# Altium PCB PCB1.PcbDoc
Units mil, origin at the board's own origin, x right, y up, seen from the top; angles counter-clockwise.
Board outline 3959.97 x 4064.97 mil, 2 copper layers (Top Layer, Bottom Layer); 11 components, 12 nets, 153 pads, 2 vias.
Unrouted connection lines stored in the file: 4.
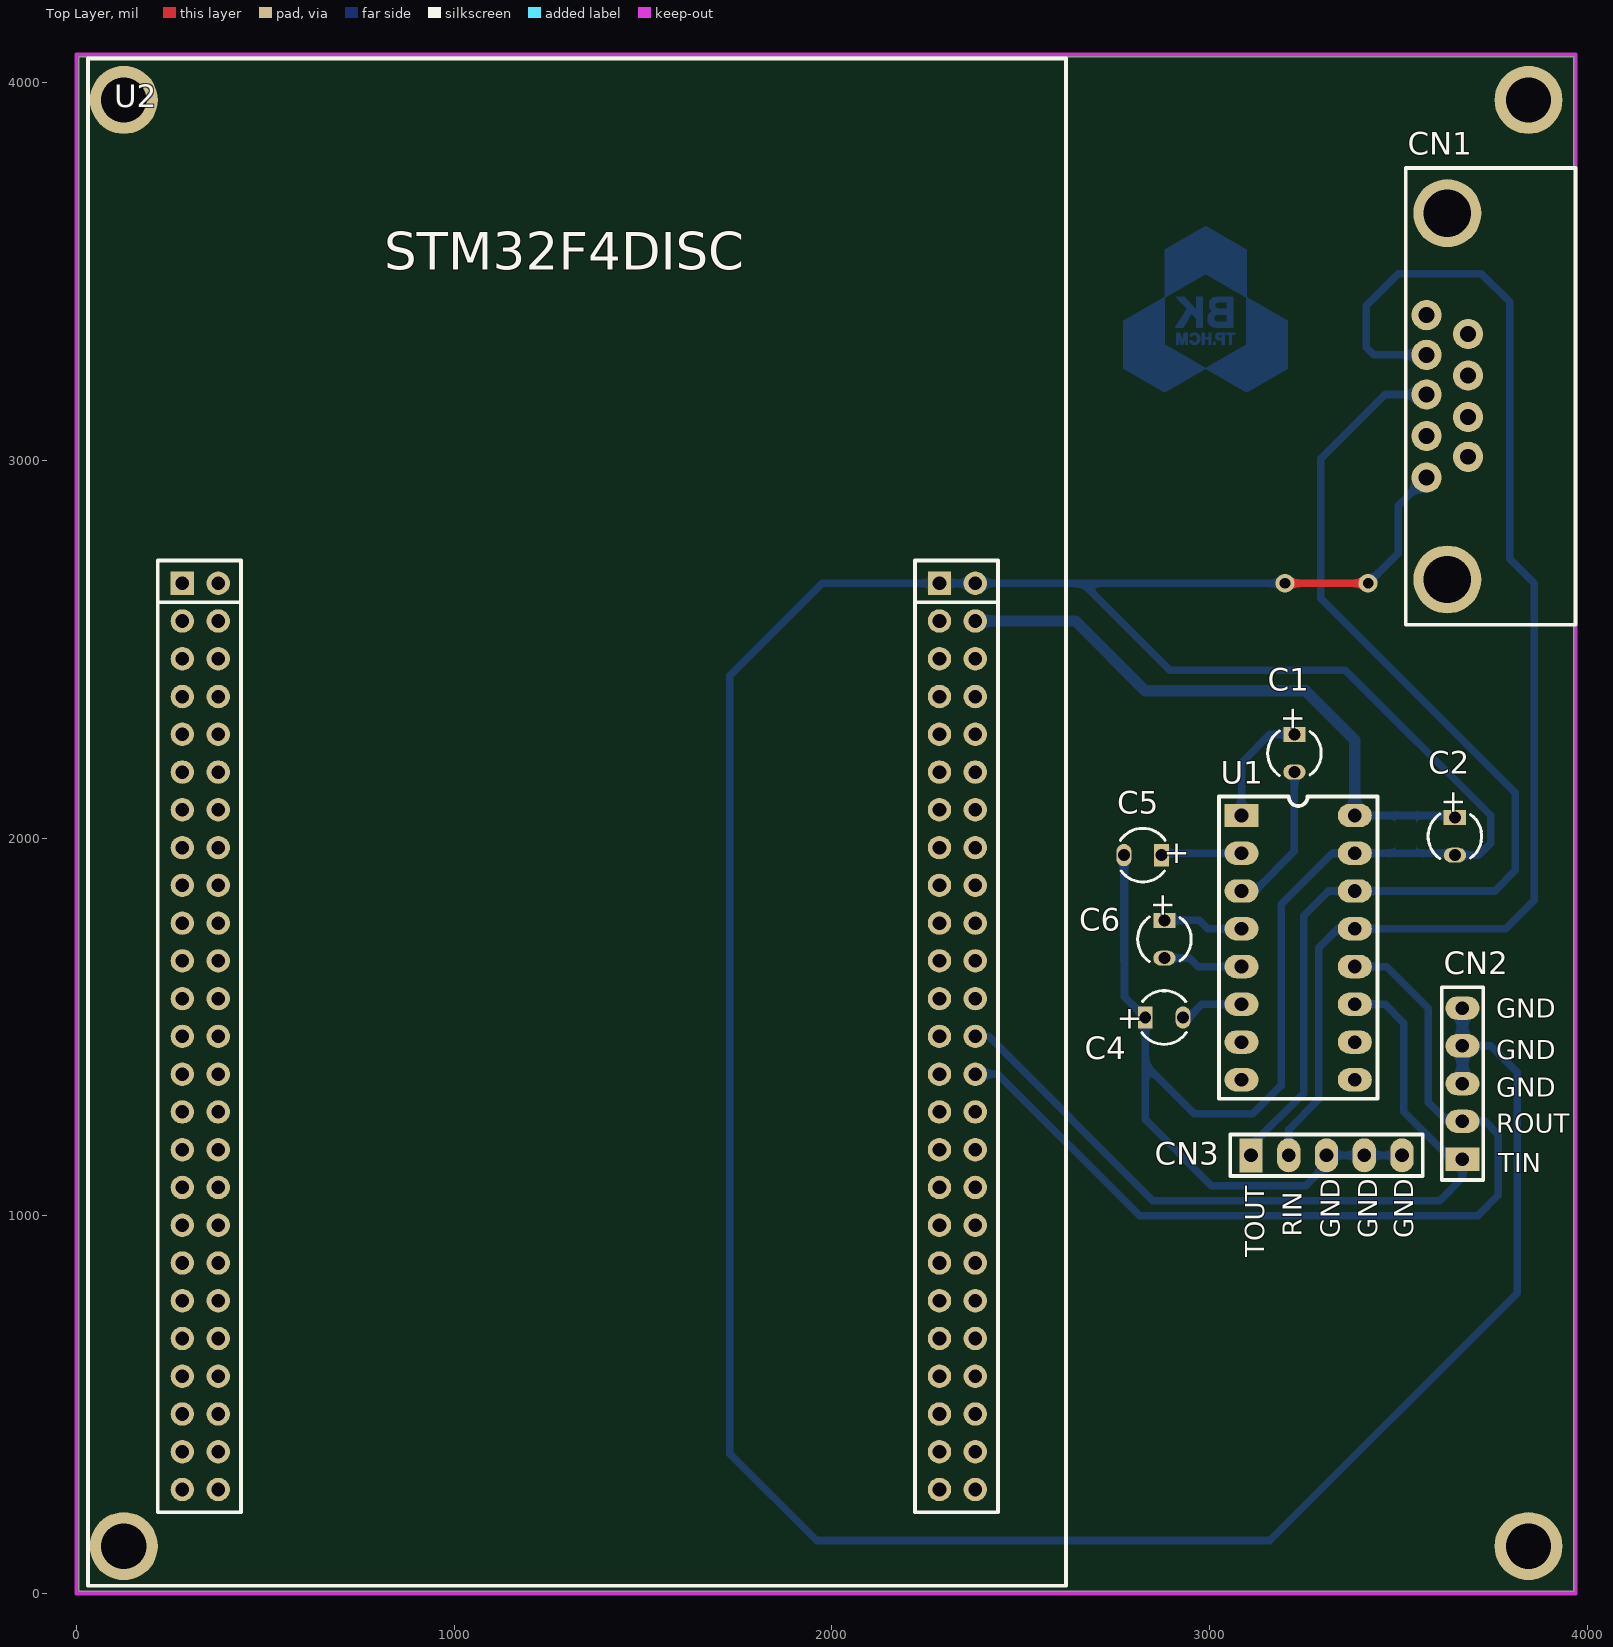
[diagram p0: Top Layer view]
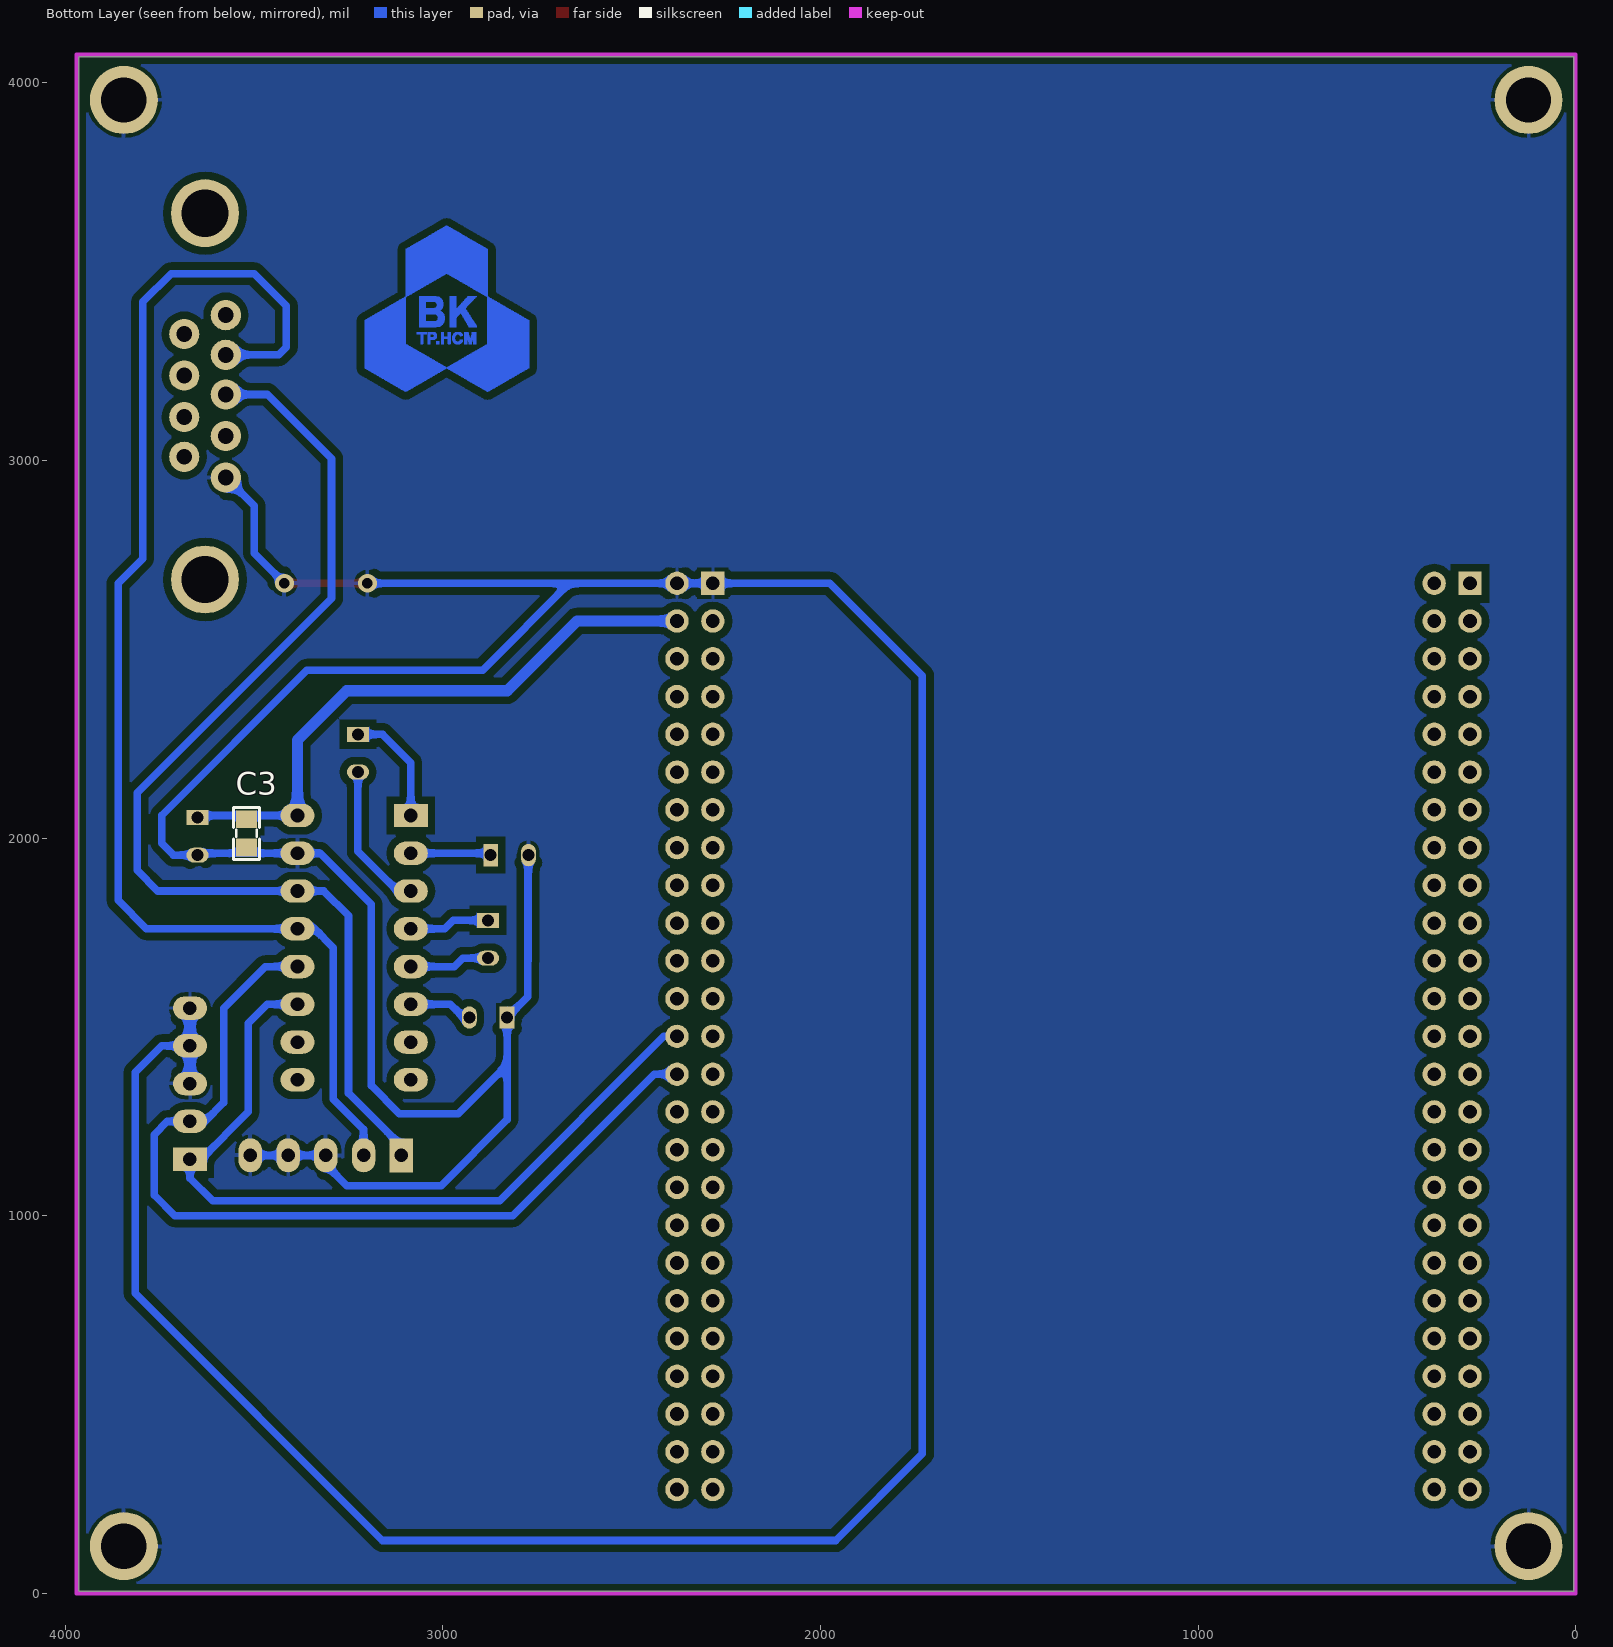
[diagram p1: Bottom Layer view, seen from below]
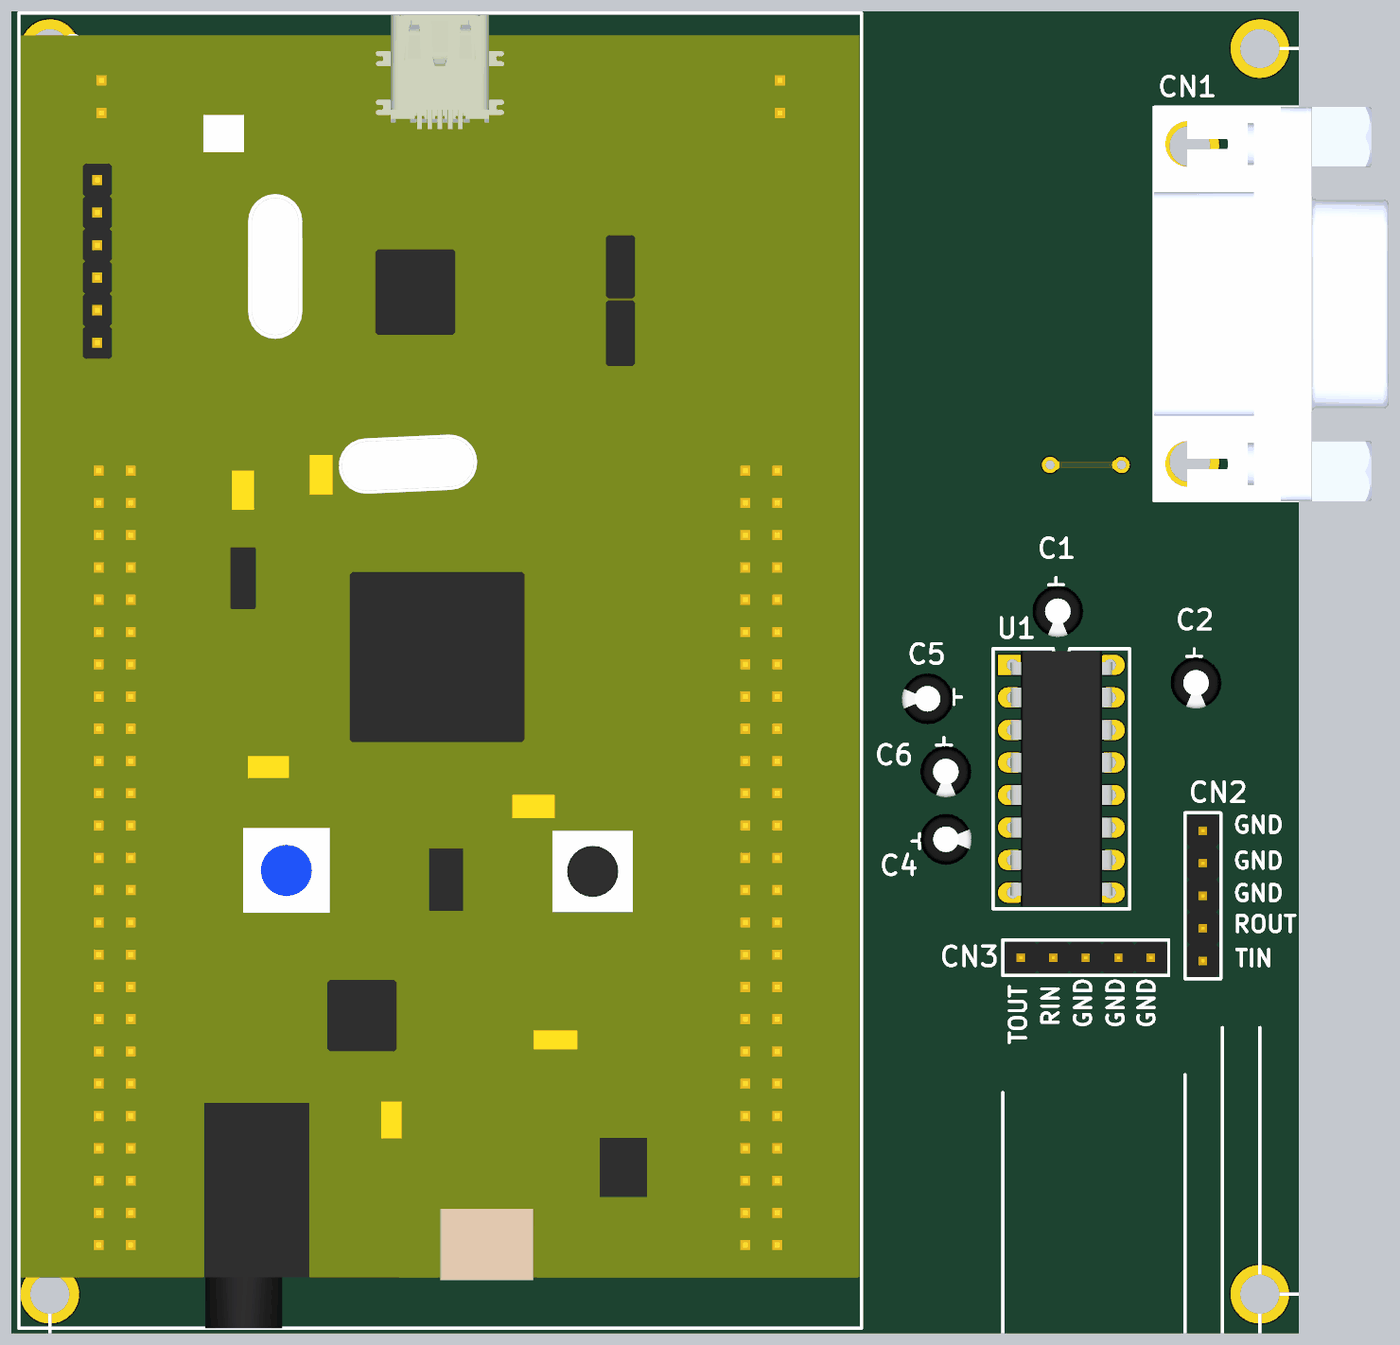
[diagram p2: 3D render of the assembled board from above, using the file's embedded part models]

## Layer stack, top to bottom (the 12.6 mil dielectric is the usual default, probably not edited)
Top Solder: solder mask 0.4, Solder Resist, Dk 3.5
Top Layer: signal copper 1.4
Dielectric 1: dielectric 12.6, FR-4, Dk 4.8
Bottom Layer: signal copper 1.4
Bottom Solder: solder mask 0.4, Solder Resist, Dk 3.5

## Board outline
5.01,5.01 5.01,4069.99 3964.98,4069.99 3964.98,5.02

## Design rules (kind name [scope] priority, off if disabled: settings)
Clearance [All] p1: gap=20 ignorepadtopadclearanceinfootprint=FALSE
PolygonConnect [All] p1: connectstyle=Relief reliefconductorwidth=10 reliefentries=4 polygonreliefangle="90 Angle" airgapwidth=10
RoutingVias [All] p1: holewidth=28 width=50 viastyle="Through Hole" minholewidth=28 minwidth=50 maxholewidth=28 maxwidth=50
SolderMaskExpansion [All] p1: expansion=4
Width [All] p1: maxlimit=40 minlimit=20 preferedwidth=30
30 further rules are at their usual default settings.

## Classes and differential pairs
component class Schematic: C1 C2 C3 C4 C5 C6 CN1 CN2 CN3 U1

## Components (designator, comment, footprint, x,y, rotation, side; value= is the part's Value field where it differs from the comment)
C1 "1uF" "TU HOA 3MM" 3225,2225 r270 top value=8-Jun-2000
C2 "1uF" "TU HOA 3MM" 3650,2005 r270 top value=8-Jun-2000
C3 "104" "tu 0805" 3520.13,2012.43 r90 bottom
C4 "1uF" "TU HOA 3MM" 2880,1525 r0 top value=8-Jun-2000
C5 "1uF" "TU HOA 3MM" 2823.46,1955 r180 top value=8-Jun-2000
C6 "1uF" "TU HOA 3MM" 2880.72,1732.25 r270 top value=8-Jun-2000
CN1 "DB9 Terminal" DB9 3575,2805 r90 top
CN2 "Header 5p" "HEADER 5P MALE" 3670,1150 r180 top
CN3 "Header 5p" "HEADER 5P MALE" 3110,1160 r90 top
U1 "MAX232" DIP16 3085,2060 r0 top
U2 "STM32F4 DISC" "STM32F4 DISC" 280,2675 r0 top

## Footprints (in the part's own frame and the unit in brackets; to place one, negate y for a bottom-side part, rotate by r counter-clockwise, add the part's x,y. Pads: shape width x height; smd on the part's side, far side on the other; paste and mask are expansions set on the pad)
DB9 [mil]
  round 80 hole 42: 1(580,0) 2(475,0) 3(370,0) 4(260,0) 5(150,0) 6(530,-110) 7(420,-110) 8(310,-110) 9(205,-110)
  round 180 hole 125: ""(-120,-55) ""(850,-55)
  silkscreen extent -240,-395 970,55, body extent -241,-665 971,55, height 547
DIP16 [mil]
  rect 90x62 hole 36: 1(0,0)
  oval 90x62 hole 36: 2(0,-100) 3(0,-200) 4(0,-300) 5(0,-400) 6(0,-500) 7(0,-600) 8(0,-700) 9(300,-700) 10(300,-600) 11(300,-500) 12(300,-400) 13(300,-300) 14(300,-200) 15(300,-100) 16(300,0)
  silkscreen extent -60,-750 360,50, body extent -6,-743 306,43, height 179
"HEADER 5P MALE" [mil]
  rect 90x62 hole 36: 1(0,0)
  oval 90x62 hole 36: 2(0,-100) 3(0,-200) 4(0,-300) 5(0,-400)
  silkscreen extent -55,-455 55,55, body extent -50,-450 50,50, height 350
"STM32F4 DISC" [mil]
  rect 62x62 hole 36: 1(0,0) 51(2005,0)
  round 62 hole 36: 2(95,0) 3(0,-100) 4(95,-100) 5(0,-200) 6(95,-200) 7(0,-300) 8(95,-300) 9(0,-400) 10(95,-400) 11(0,-500) 12(95,-500) 13(0,-600) 14(95,-600) 15(0,-700) 16(95,-700) 17(0,-800) 18(95,-800) 19(0,-900) 20(95,-900) 21(0,-1000) 22(95,-1000) 23(0,-1100) 24(95,-1100) 25(0,-1200) 26(95,-1200) 27(0,-1300) 28(95,-1300) 29(0,-1400) 30(95,-1400) 31(0,-1500) 32(95,-1500) 33(0,-1600) 34(95,-1600) 35(0,-1700) 36(95,-1700) 37(0,-1800) 38(95,-1800) 39(0,-1900) 40(95,-1900) 41(0,-2000) 42(95,-2000) 43(0,-2100) 44(95,-2100) 45(0,-2200) 46(95,-2200) 47(0,-2300) 48(95,-2300) 49(0,-2400) 50(95,-2400) 52(2100,0) 53(2005,-100) 54(2100,-100) 55(2005,-200) 56(2100,-200) 57(2005,-300) 58(2100,-300) 59(2005,-400) 60(2100,-400) 61(2005,-500) 62(2100,-500) 63(2005,-600) 64(2100,-600) 65(2005,-700) 66(2100,-700) 67(2005,-800) 68(2100,-800) 69(2005,-900) 70(2100,-900) 71(2005,-1000) 72(2100,-1000) 73(2005,-1100) 74(2100,-1100) 75(2005,-1200) 76(2100,-1200) 77(2005,-1300) 78(2100,-1300) 79(2005,-1400) 80(2100,-1400) 81(2005,-1500) 82(2100,-1500) 83(2005,-1600) 84(2100,-1600) 85(2005,-1700) 86(2100,-1700) 87(2005,-1800) 88(2100,-1800) 89(2005,-1900) 90(2100,-1900) 91(2005,-2000) 92(2100,-2000) 93(2005,-2100) 94(2100,-2100) 95(2005,-2200) 96(2100,-2200) 97(2005,-2300) 98(2100,-2300) 99(2005,-2400) 100(2100,-2400)
  silkscreen extent -250,-2655 2340,1390, body extent -245,-2655 2334,1383, height 731
"tu 0805" [mm] "Compoment SMD 80x50mil"
  rect 1.2x1.4 smd: 1(-0.946,-0.003) 2(0.954,-0.003)
  silkscreen extent -1.75,-0.89 1.75,0.89, body extent -1.01,-0.64 1.01,0.63, height 0.61
"TU HOA 3MM" [mm]
  rect 1x1.5 hole 0.8: 1(-1.27,0)
  oval 1x1.5 hole 0.8: 2(1.27,0)
  silkscreen extent -1.5,-1.81 1.5,1.8, body extent -2,-2.03 1.99,1.97, height 7.01

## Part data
C1 C2 C4 C5 C6: library part "Tu 3mm", "C?m"
C3: library part "Tu 0805 104 50V 10%", "Dán"
U2: "STM32F4 Discovery board. Chip on Board is Stm32f411VET6. Speed is 150MHz"

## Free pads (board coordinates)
  round 180 hole 120: ""(125,125) ""(125,3955) ""(3845,125) ""(3845,3955)

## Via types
v1: diameter 50, hole 28, Top Layer to Bottom Layer, 2 vias

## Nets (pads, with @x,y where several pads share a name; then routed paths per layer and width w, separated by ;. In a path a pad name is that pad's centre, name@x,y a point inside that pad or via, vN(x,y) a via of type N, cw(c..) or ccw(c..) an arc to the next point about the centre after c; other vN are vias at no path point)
+5: C2.1 C3.2 U1.16 U2.54 | length 1602.5
  Bottom Layer w20: U1.16 3645,2060 C2.1
  Bottom Layer w30: U2.54 2645,2575 2830,2390 3255,2390 3385,2260 U1.16
GND: C2.2 C3.1 C4.1 C5.2 CN1.5 CN2.3 CN2.4 CN2.5 CN3.3 CN3.4 CN3.5 pad. U1.15 U2.51 U2.52 | length 12369.1
  Top Layer w20: v1(3200,2675) v1(3420,2675)
  Bottom Layer w20: 2773.46,1675 C5.2 2775,1953.46 2775,1580 C4.1 2830,1400 ; v1(3200,2675) 2665,2675 ; v1(3420,2675) 3500,2755 3500,2880 CN1.5 ; CN3.5 CN3.4 CN3.3 3310,1135 3255,1080 3005,1080 2830,1255 2830,1400 ; CN2.4 3745,1450 3815,1380 3815,795 3160,140 1960,140 1730,370 1730,2430 1975,2675 U2.51 U2.52 2665,2675 ; 2665,2675 2895,2445 3360,2445 3745,2060 3745,1986.57 3713.43,1955 C2.2 3645,1960 U1.15 3325,1960 3190,1825 3190,1345 3115,1270 2960,1270 2830,1400
  Bottom Layer w30: CN2.3 CN2.4 CN2.5
NetC1_1: C1.1 U1.1 | length 311.1
  Bottom Layer w20: U1.1 3085,2200 3160,2275 C1.1
NetC1_2: C1.2 U1.3 | length 393.5
  Bottom Layer w20: U1.3 3120,1860 3225,1965 C1.2
NetC4_2: C4.2 U1.6 | length 169.5
  Bottom Layer w20: C4.2 2945,1525 2980,1560 U1.6
NetC5_1: C5.1 U1.2 | length 213.6
  Bottom Layer w20: C5.1 2878.46,1960 U1.2
NetC6_1: C6.1 U1.4 | length 213.5
  Bottom Layer w20: C6.1 2972.75,1782.25 2995,1760 U1.4
NetC6_2: C6.2 U1.5 | length 213.5
  Bottom Layer w20: C6.2 2947.75,1682.25 2970,1660 U1.5
R1IN: CN1.2 CN3.2 U1.13 | length 3541.4
  Bottom Layer w20: CN3.2 3210,1228.43 3290,1308.43 3290,1710 3340,1760 U1.13 3785,1760 3860,1835 3860,2675 3795,2740 3795,3420 3720,3495 3500,3495 3415,3410 3415,3300 3435,3280 CN1.2
R1OUT: CN2.2 U1.12 U2.78 | length 2433.9
  Bottom Layer w20: U2.78 2440,1375 2815,1000 3710,1000 3765,1055 3765,1215 3730,1250 CN2.2 3630,1250 3580,1300 3580,1550 3470,1660 U1.12
T1IN: CN2.1 U1.11 U2.76 | length 2137.5
  Bottom Layer w20: U2.76 2415,1475 2850,1040 3610,1040 3670,1100 CN2.1 3640,1150 3515,1275 3515,1510 3465,1560 U1.11
T1OUT: CN1.3 CN3.1 U1.14 | length 2956.4
  Bottom Layer w20: CN3.1 3110,1185 3250,1325 3250,1795 3315,1860 U1.14 3755,1860 3810,1915 3810,2120 3295,2635 3295,3005 3465,3175 CN1.3
pads on no net: CN1. CN1.1 CN1.4 CN1.6 CN1.7 CN1.8 CN1.9 U1.7 U1.8 U1.9 U1.10 U2.1 U2.2 U2.3 U2.4 U2.5 U2.6 U2.7 U2.8 U2.9 U2.10 U2.11 U2.12 U2.13 U2.14 U2.15 U2.16 U2.17 U2.18 U2.19 U2.20 U2.21 U2.22 U2.23 U2.24 U2.25 U2.26 U2.27 U2.28 U2.29 U2.30 U2.31 U2.32 U2.33 U2.34 U2.35 U2.36 U2.37 U2.38 U2.39 U2.40 U2.41 U2.42 U2.43 U2.44 U2.45 U2.46 U2.47 U2.48 U2.49 U2.50 U2.53 U2.55 U2.56 U2.57 U2.58 U2.59 U2.60 U2.61 U2.62 U2.63 U2.64 U2.65 U2.66 U2.67 U2.68 U2.69 U2.70 U2.71 U2.72 U2.73 U2.74 U2.75 U2.77 U2.79 U2.80 U2.81 U2.82 U2.83 U2.84 U2.85 U2.86 U2.87 U2.88 U2.89 U2.90 U2.91 U2.92 U2.93 U2.94 U2.95 U2.96 U2.97 U2.98 U2.99 U2.100
copper on no net: | length 92448
  Bottom Layer w1: 2772,3245 3207,3245 ; 2772,3246 2989,3246 ; 2772,3247 2987,3247 ; 2772,3248 2985,3248 ; 2772,3249 2983,3249 ; 2772,3250 2982,3250 ; 2772,3251 2980,3251 ; 2772,3252 2978,3252 ; 2772,3253 2976,3253 ; 2772,3254 2975,3254 ; 2772,3255 2973,3255 ; 2772,3256 2971,3256 ; 2772,3257 2970,3257 ; 2772,3258 2968,3258 ; 2772,3259 2966,3259 ; 2772,3260 2964,3260 ; 2772,3261 2963,3261 ; 2772,3262 2961,3262 ; 2772,3263 2959,3263 ; 2772,3264 2957,3264 ; 2772,3265 2956,3265 ; 2772,3266 2954,3266 ; 2772,3267 2952,3267 ; 2772,3268 2950,3268 ; 2772,3269 2949,3269 ; 2772,3270 2947,3270 ; 2772,3271 2945,3271 ; 2772,3272 2944,3272 ; 2772,3273 2942,3273 ; 2772,3274 2940,3274 ; 2772,3275 2938,3275 ; 2772,3276 2937,3276 ; 2772,3277 2935,3277 ; 2772,3278 2933,3278 ; 2772,3279 2931,3279 ; 2772,3280 2930,3280 ; 2772,3281 2928,3281 ; 2772,3282 2926,3282 ; 2772,3283 2924,3283 ; 2772,3284 2923,3284 ; 2772,3285 2921,3285 ; 2772,3286 2919,3286 ; 2772,3287 2918,3287 ; 2772,3288 2916,3288 ; 2772,3289 2914,3289 ; 2772,3290 2912,3290 ; 2772,3291 2911,3291 ; 2772,3292 2909,3292 ; 2772,3293 2907,3293 ; 2772,3294 2905,3294 ; 2772,3295 2904,3295 ; 2772,3296 2902,3296 ; 2772,3297 2900,3297 ; 2772,3298 2899,3298 ; 2772,3299 2897,3299 ; 2772,3300 2895,3300 ; 2772,3301 2893,3301 ; 2772,3302 2892,3302 ; 2772,3303 2890,3303 ; 2772,3304 2888,3304 ; 2772,3305 2886,3305 ; 2772,3306 2885,3306 ; 2772,3307 2883,3307 ; 2772,3308 2882,3308 ; 2772,3309 2882,3309 ; 2772,3310 2882,3310 ; 2772,3311 2882,3311 ; 2772,3312 2882,3312 ; 2772,3313 2882,3313 ; 2772,3314 2882,3314 ; 2772,3315 2882,3315 ; 2772,3316 2882,3316 ; 2772,3317 2882,3317 ; 2772,3318 2882,3318 ; 2772,3319 2882,3319 ; 2772,3320 2882,3320 ; 2772,3321 2882,3321 ; 2772,3322 2882,3322 ; 2772,3323 2882,3323 ; 2772,3324 2882,3324 ; 2772,3325 2882,3325 ; 2772,3326 2882,3326 ; 2772,3327 2882,3327 ; 2772,3328 2882,3328 ; 2772,3329 2882,3329 ; 2772,3330 2882,3330 ; 2772,3331 2882,3331 ; 2772,3332 2882,3332 ; 2772,3333 2882,3333 ; 2772,3334 2882,3334 ; 2772,3335 2882,3335 ; 2772,3336 2882,3336 ; 2772,3337 2882,3337 ; 2772,3338 2882,3338 ; 2772,3339 2882,3339 ; 2772,3340 2882,3340 ; 2772,3341 2882,3341 ; 2772,3342 2882,3342 ; 2772,3343 2882,3343 ; 2772,3344 2882,3344 ; 2772,3345 2882,3345 ; 2772,3346 2882,3346 ; 2772,3347 2882,3347 ; 2772,3348 2882,3348 ; 2772,3349 2882,3349 ; 2772,3350 2882,3350 ; 2772,3351 2882,3351 ; 2772,3352 2882,3352 ; 2772,3353 2882,3353 ; 2772,3354 2882,3354 ; 2772,3355 2882,3355 ; 2772,3356 2882,3356 ; 2772,3357 2882,3357 ; 2772,3358 2882,3358 ; 2772,3359 2882,3359 ; 2772,3360 2882,3360 ; 2772,3361 2882,3361 ; 2772,3362 2882,3362 ; 2772,3363 2882,3363 ; 2772,3364 2882,3364 ; 2772,3365 2882,3365 ; 2772,3366 2882,3366 ; 2772,3367 2882,3367 ; 2772,3368 2882,3368 ; 2772,3369 2882,3369 ; 2772,3370 2882,3370 ; 2773,3244 3207,3244 ; 2774,3371 2882,3371 ; 2775,3243 2988,3243 ; 2775,3372 2882,3372 ; 2777,3242 2986,3242 ; 2777,3373 2882,3373 ; 2778,3241 2984,3241 ; 2779,3374 2882,3374 ; 2780,3240 2983,3240 ; 2780,3375 2882,3375 ; 2782,3239 2981,3239 ; 2782,3376 2882,3376 ; 2784,3238 2979,3238 ; 2784,3377 2882,3377 ; 2785,3237 2977,3237 ; 2786,3378 2882,3378 ; 2787,3236 2976,3236 ; 2787,3379 2882,3379 ; 2789,3235 2974,3235 ; 2789,3380 2882,3380 ; 2791,3234 2972,3234 ; 2791,3381 2882,3381 ; 2792,3233 2970,3233 ; 2793,3382 2882,3382 ; 2794,3232 2969,3232 ; 2794,3383 2882,3383 ; 2796,3231 2967,3231 ; 2796,3384 2882,3384 ; 2798,3230 2965,3230 ; 2798,3385 2882,3385 ; 2799,3229 2963,3229 ; 2799,3386 2882,3386 ; 2801,3228 2962,3228 ; 2801,3387 2882,3387 ; 2803,3227 2960,3227 ; 2803,3388 2882,3388 ; 2804,3226 2958,3226 ; 2805,3389 2882,3389 ; 2806,3225 2957,3225 ; 2806,3390 2882,3390 ; 2808,3224 2955,3224 ; 2808,3391 2882,3391 ; 2810,3223 2953,3223 ; 2810,3392 2882,3392 ; 2811,3222 2951,3222 ; 2812,3393 2882,3393 ; 2813,3221 2950,3221 ; 2813,3394 2882,3394 ; 2815,3220 2948,3220 ; 2815,3395 2882,3395 ; 2817,3219 2946,3219 ; 2817,3396 2882,3396 ; 2818,3218 2944,3218 ; 2819,3397 2882,3397 ; 2820,3217 2943,3217 ; 2820,3398 2882,3398 ; 2822,3216 2941,3216 ; 2822,3399 2882,3399 ; 2824,3215 2939,3215 ; 2824,3400 2882,3400 ; 2825,3214 2937,3214 ; 2825,3401 2882,3401 ; 2827,3213 2936,3213 ; 2827,3402 2882,3402 ; 2829,3212 2934,3212 ; 2829,3403 2882,3403 ; 2830,3211 2932,3211 ; 2831,3404 2882,3404 ; 2832,3210 2931,3210 ; 2832,3405 2882,3405 ; 2834,3209 2929,3209 ; 2834,3406 2882,3406 ; 2836,3208 2927,3208 ; 2836,3407 2882,3407 ; 2837,3207 2925,3207 ; 2838,3408 2882,3408 ; 2839,3206 2924,3206 ; 2839,3409 2882,3409 ; 2841,3205 2922,3205 ; 2841,3410 2882,3410 ; 2843,3204 2920,3204 ; 2843,3411 2882,3411 ; 2844,3203 2918,3203 ; 2845,3412 2882,3412 ; 2846,3202 2917,3202 ; 2846,3413 2882,3413 ; 2848,3201 2915,3201 ; 2848,3414 2882,3414 ; 2849,3200 2913,3200 ; 2850,3415 2882,3415 ; 2851,3199 2911,3199 ; 2851,3416 2882,3416 ; 2853,3198 2910,3198 ; 2853,3417 2882,3417 ; 2855,3197 2908,3197 ; 2855,3418 2882,3418 ; 2856,3196 2906,3196 ; 2857,3419 2882,3419 ; 2858,3195 2905,3195 ; 2858,3420 2882,3420 ; 2860,3194 2903,3194 ; 2860,3421 2882,3421 ; 2862,3193 2901,3193 ; 2862,3422 2882,3422 ; 2863,3192 2899,3192 ; 2864,3423 2882,3423 ; 2865,3191 2898,3191 ; 2865,3424 2882,3424 ; 2867,3190 2896,3190 ; 2867,3425 2882,3425 ; 2869,3189 2894,3189 ; 2869,3426 2882,3426 ; 2870,3188 2892,3188 ; 2870,3427 2882,3427 ; 2872,3187 2891,3187 ; 2872,3428 2882,3428 ; 2874,3186 2889,3186 ; 2874,3429 2882,3429 ; 2875,3185 2887,3185 ; 2876,3430 2882,3430 ; 2877,3184 2885,3184 ; 2877,3431 2882,3431 ; 2879,3183 2884,3183 ; 2879,3432 2882,3432 ; 2881,3182 2882,3182 ; 2881,3433 2883,3433 ; 2881,3434 2884,3434 ; 2881,3435 2886,3435 ; 2881,3436 2888,3436 ; 2881,3437 2889,3437 ; 2881,3438 2891,3438 ; 2881,3439 2893,3439 ; 2881,3440 2895,3440 ; 2881,3441 2896,3441 ; 2881,3442 2898,3442 ; 2881,3443 2900,3443 ; 2881,3444 2902,3444 ; 2881,3445 2903,3445 ; 2881,3446 2905,3446 ; 2881,3447 2907,3447 ; 2881,3448 2909,3448 ; 2881,3449 2910,3449 ; 2881,3450 2912,3450 ; 2881,3451 2914,3451 ; 2881,3452 2915,3452 ; 2881,3453 2917,3453 ; 2881,3454 2919,3454 ; 2881,3455 2921,3455 ; 2881,3456 2922,3456 ; 2881,3457 2924,3457 ; 2881,3458 2926,3458 ; 2881,3459 2928,3459 ; 2881,3460 2929,3460 ; 2881,3461 2931,3461 ; 2881,3462 2933,3462 ; 2881,3463 2934,3463 ; 2881,3464 2936,3464 ; 2881,3465 2938,3465 ; 2881,3466 2940,3466 ; 2881,3467 2941,3467 ; 2881,3468 2943,3468 ; 2881,3469 2945,3469 ; 2881,3470 2947,3470 ; 2881,3471 2948,3471 ; 2881,3472 2950,3472 ; 2881,3473 2952,3473 ; 2881,3474 2954,3474 ; 2881,3475 2955,3475 ; 2881,3476 2957,3476 ; 2881,3477 2959,3477 ; 2881,3478 2960,3478 ; 2881,3479 2962,3479 ; 2881,3480 2964,3480 ; 2881,3481 2966,3481 ; 2881,3482 2967,3482 ; 2881,3483 2969,3483 ; 2881,3484 2971,3484 ; 2881,3485 2973,3485 ; 2881,3486 2974,3486 ; 2881,3487 2976,3487 ; 2881,3488 2978,3488 ; 2881,3489 2980,3489 ; 2881,3490 2981,3490 ; 2881,3491 2983,3491 ; 2881,3492 2985,3492 ; 2881,3493 2986,3493 ; 2881,3494 2988,3494 ; 2881,3495 3099,3495 ; 2881,3496 3099,3496 ; 2881,3497 3099,3497 ; 2881,3498 3099,3498 ; 2881,3499 3099,3499 ; 2881,3500 3099,3500 ; 2881,3501 3099,3501 ; 2881,3502 3099,3502 ; 2881,3503 3099,3503 ; 2881,3504 3099,3504 ; 2881,3505 3099,3505 ; 2881,3506 3099,3506 ; 2881,3507 3099,3507 ; 2881,3508 3099,3508 ; 2881,3509 3099,3509 ; 2881,3510 3099,3510 ; 2881,3511 3099,3511 ; 2881,3512 3099,3512 ; 2881,3513 3099,3513 ; 2881,3514 3099,3514 ; 2881,3515 3099,3515 ; 2881,3516 3099,3516 ; 2881,3517 3099,3517 ; 2881,3518 3099,3518 ; 2881,3519 3099,3519 ; 2881,3520 3099,3520 ; 2881,3521 3099,3521 ; 2881,3522 3099,3522 ; 2881,3523 3099,3523 ; 2881,3524 3099,3524 ; 2881,3525 3099,3525 ; 2881,3526 3099,3526 ; 2881,3527 3099,3527 ; 2881,3528 3099,3528 ; 2881,3529 3099,3529 ; 2881,3530 3099,3530 ; 2881,3531 3099,3531 ; 2881,3532 3099,3532 ; 2881,3533 3099,3533 ; 2881,3534 3099,3534 ; 2881,3535 3099,3535 ; 2881,3536 3099,3536 ; 2881,3537 3099,3537 ; 2881,3538 3099,3538 ; 2881,3539 3099,3539 ; 2881,3540 3099,3540 ; 2881,3541 3099,3541 ; 2881,3542 3099,3542 ; 2881,3543 3099,3543 ; 2881,3544 3099,3544 ; 2881,3545 3099,3545 ; 2881,3546 3099,3546 ; 2881,3547 3099,3547 ; 2881,3548 3099,3548 ; 2881,3549 3099,3549 ; 2881,3550 3099,3550 ; 2881,3551 3099,3551 ; 2881,3552 3099,3552 ; 2881,3553 3099,3553 ; 2881,3554 3099,3554 ; 2881,3555 3099,3555 ; 2881,3556 3099,3556 ; 2881,3557 3099,3557 ; 2881,3558 3099,3558 ; 2882,3559 3098,3559 ; 2884,3560 3096,3560 ; 2885,3561 3094,3561 ; 2887,3562 3093,3562 ; 2889,3563 3091,3563 ; 2891,3564 3089,3564 ; 2892,3565 3087,3565 ; 2894,3566 3086,3566 ; 2896,3567 3084,3567 ; 2898,3568 3082,3568 ; 2899,3569 3081,3569 ; 2901,3570 3079,3570 ; 2903,3571 3077,3571 ; 2905,3572 3075,3572 ; 2906,3573 3074,3573 ; 2908,3574 3072,3574 ; 2910,3353 2931,3353 ; 2910,3354 2932,3354 ; 2910,3355 2932,3355 ; 2910,3575 3070,3575 ; 2911,3356 2933,3356 ; 2911,3434 2934,3434 ; 2911,3576 3068,3576 ; 2912,3308 2919,3308 ; 2912,3309 2919,3309 ; 2912,3310 2919,3310 ; 2912,3311 2919,3311 ; 2912,3312 2919,3312 ; 2912,3313 2919,3313 ; 2912,3314 2919,3314 ; 2912,3315 2919,3315 ; 2912,3316 2919,3316 ; 2912,3317 2919,3317 ; 2912,3318 2919,3318 ; 2912,3319 2919,3319 ; 2912,3320 2919,3320 ; 2912,3321 2919,3321 ; 2912,3322 2919,3322 ; 2912,3323 2919,3323 ; 2912,3324 2919,3324 ; 2912,3325 2919,3325 ; 2912,3326 2919,3326 ; 2912,3327 2926,3327 ; 2912,3328 2925,3328 ; 2912,3329 2925,3329 ; 2912,3330 2925,3330 ; 2912,3331 2925,3331 ; 2912,3332 2924,3332 ; 2912,3333 2924,3333 ; 2912,3334 2924,3334 ; 2912,3335 2923,3335 ; 2912,3336 2923,3336 ; 2912,3337 2923,3337 ; 2912,3338 2923,3338 ; 2912,3357 2933,3357 ; 2912,3358 2934,3358 ; 2912,3433 2935,3433 ; 2913,3339 2922,3339 ; 2913,3359 2934,3359 ; 2913,3432 2935,3432 ; 2913,3577 3067,3577 ; 2914,3360 2935,3360 ; 2914,3361 2936,3361 ; 2914,3431 2936,3431 ; 2915,3362 2936,3362 ; 2915,3430 2937,3430 ; 2915,3578 3065,3578 ; 2916,3363 2937,3363 ; 2916,3364 2937,3364 ; 2916,3429 2938,3429 ; 2917,3365 2938,3365 ; 2917,3366 2938,3366 ; 2917,3428 2939,3428 ; 2917,3579 3063,3579 ; 2918,3367 2939,3367 ; 2918,3426 2941,3426 ; 2918,3427 2940,3427 ; 2918,3580 3061,3580 ; 2919,3368 2940,3368 ; 2919,3369 2940,3369 ; 2919,3425 2942,3425 ; 2920,3323 2927,3323 ; 2920,3324 2926,3324 ; 2920,3325 2926,3325 ; 2920,3326 2926,3326 ; 2920,3370 2941,3370 ; 2920,3424 2943,3424 ; 2920,3581 3060,3581 ; 2921,3319 2934,3319 ; 2921,3320 2927,3320 ; 2921,3321 2927,3321 ; 2921,3322 2927,3322 ; 2921,3371 2941,3371 ; 2921,3372 2942,3372 ; 2921,3423 2944,3423 ; 2922,3315 2933,3315 ; 2922,3316 2933,3316 ; 2922,3317 2933,3317 ; 2922,3318 2934,3318 ; 2922,3373 2942,3373 ; 2922,3422 2944,3422 ; 2922,3582 3058,3582 ; 2923,3311 2932,3311 ; 2923,3312 2932,3312 ; 2923,3313 2932,3313 ; 2923,3314 2933,3314 ; 2923,3374 2943,3374 ; 2923,3375 2944,3375 ; 2923,3421 2945,3421 ; 2924,3308 2931,3308 ; 2924,3309 2931,3309 ; 2924,3310 2932,3310 ; 2924,3376 2944,3376 ; 2924,3420 2946,3420 ; 2924,3583 3056,3583 ; 2925,3377 2945,3377 ; 2925,3378 2945,3378 ; 2925,3419 2947,3419 ; 2925,3584 3055,3584 ; 2926,3379 2946,3379 ; 2926,3380 2947,3380 ; 2926,3418 2948,3418 ; 2927,3381 2947,3381 ; 2927,3417 2949,3417 ; 2927,3585 3053,3585 ; 2928,3320 2934,3320 ; 2928,3321 2934,3321 ; 2928,3322 2935,3322 ; 2928,3382 2948,3382 ; 2928,3383 2948,3383 ; 2928,3416 2950,3416 ; 2929,3323 2935,3323 ; 2929,3324 2935,3324 ; 2929,3325 2935,3325 ; 2929,3326 2935,3326 ; 2929,3384 2949,3384 ; 2929,3415 2951,3415 ; 2929,3586 3051,3586 ; 2930,3327 2943,3327 ; 2930,3328 2943,3328 ; 2930,3329 2943,3329 ; 2930,3330 2943,3330 ; 2930,3385 2949,3385 ; 2930,3386 2950,3386 ; 2930,3414 2952,3414 ; 2931,3331 2943,3331 ; 2931,3332 2943,3332 ; 2931,3333 2943,3333 ; 2931,3334 2943,3334 ; 2931,3387 2951,3387 ; 2931,3413 2953,3413 ; 2931,3587 3049,3587 ; 2932,3335 2943,3335 ; 2932,3336 2943,3336 ; 2932,3337 2943,3337 ; 2932,3388 2951,3388 ; 2932,3389 2952,3389 ; 2932,3412 2953,3412 ; 2932,3588 3048,3588 ; 2933,3338 2943,3338 ; 2933,3339 2943,3339 ; 2933,3390 2952,3390 ; 2933,3391 2982,3391 ; 2933,3411 2954,3411 ; 2934,3392 2982,3392 ; 2934,3410 2955,3410 ; 2934,3589 3046,3589 ; 2935,3393 2982,3393 ; 2935,3394 2982,3394 ; 2935,3409 2956,3409 ; 2936,3308 2943,3308 ; 2936,3309 2943,3309 ; 2936,3310 2943,3310 ; 2936,3311 2943,3311 ; 2936,3312 2943,3312 ; 2936,3313 2943,3313 ; 2936,3314 2943,3314 ; 2936,3315 2943,3315 ; 2936,3316 2943,3316 ; 2936,3317 2943,3317 ; 2936,3318 2943,3318 ; 2936,3319 2943,3319 ; 2936,3320 2943,3320 ; 2936,3321 2943,3321 ; 2936,3322 2943,3322 ; 2936,3323 2943,3323 ; 2936,3324 2943,3324 ; 2936,3325 2943,3325 ; 2936,3326 2943,3326 ; 2936,3395 2982,3395 ; 2936,3408 2957,3408 ; 2936,3590 3044,3590 ; 2937,3396 2982,3396 ; 2937,3397 2982,3397 ; 2937,3406 2959,3406 ; 2937,3407 2958,3407 ; 2937,3591 3042,3591 ; 2938,3398 2982,3398 ; 2938,3405 2960,3405 ; 2939,3399 2982,3399 ; 2939,3400 2964,3400 ; 2939,3404 2961,3404 ; 2939,3592 3041,3592 ; 2940,3401 2963,3401 ; 2940,3403 2962,3403 ; 2941,3402 2963,3402 ; 2941,3593 3039,3593 ; 2943,3594 3037,3594 ; 2944,3595 3036,3595 ; 2946,3596 3034,3596 ; 2947,3317 2955,3317 ; 2948,3315 2956,3315 ; 2948,3316 2955,3316 ; 2948,3318 2955,3318 ; 2948,3330 2955,3330 ; 2948,3331 2955,3331 ; 2948,3332 2956,3332 ; 2948,3333 2958,3333 ; 2948,3597 3032,3597 ; 2949,3313 2972,3313 ; 2949,3314 2958,3314 ; 2949,3334 2972,3334 ; 2950,3312 2971,3312 ; 2950,3335 2971,3335 ; 2950,3336 2970,3336 ; 2950,3598 3030,3598 ; 2951,3311 2970,3311 ; 2951,3319 2954,3319 ; 2951,3337 2969,3337 ; 2951,3599 3029,3599 ; 2952,3310 2969,3310 ; 2952,3329 2954,3329 ; 2953,3309 2968,3309 ; 2953,3338 2967,3338 ; 2953,3390 2982,3390 ; 2953,3600 3027,3600 ; 2954,3389 2982,3389 ; 2955,3308 2966,3308 ; 2955,3339 2965,3339 ; 2955,3388 2982,3388 ; 2955,3601 3025,3601 ; 2956,3387 2982,3387 ; 2956,3602 3023,3602 ; 2957,3386 2982,3386 ; 2958,3385 2982,3385 ; 2958,3603 3022,3603 ; 2959,3384 2982,3384 ; 2960,3383 2982,3383 ; 2960,3604 3020,3604 ; 2961,3382 2982,3382 ; 2962,3381 2982,3381 ; 2962,3605 3018,3605 ; 2963,3333 2973,3333 ; 2963,3379 2982,3379 ; 2963,3380 2982,3380 ; 2963,3606 3016,3606 ; 2964,3314 2973,3314 ; 2964,3378 2982,3378 ; 2965,3315 2973,3315 ; 2965,3332 2973,3332 ; 2965,3353 2982,3353 ; 2965,3354 2982,3354 ; 2965,3355 2982,3355 ; 2965,3356 2982,3356 ; 2965,3357 2982,3357 ; 2965,3358 2982,3358 ; 2965,3359 2982,3359 ; 2965,3360 2982,3360 ; 2965,3361 2982,3361 ; 2965,3362 2982,3362 ; 2965,3363 2982,3363 ; 2965,3364 2982,3364 ; 2965,3365 2982,3365 ; 2965,3366 2982,3366 ; 2965,3367 2982,3367 ; 2965,3368 2982,3368 ; 2965,3369 2982,3369 ; 2965,3370 2982,3370 ; 2965,3371 2982,3371 ; 2965,3372 2982,3372 ; 2965,3373 2982,3373 ; 2965,3374 2982,3374 ; 2965,3375 2982,3375 ; 2965,3376 2982,3376 ; 2965,3377 2982,3377 ; 2965,3400 2982,3400 ; 2965,3401 2982,3401 ; 2965,3402 2982,3402 ; 2965,3403 2982,3403 ; 2965,3404 2982,3404 ; 2965,3405 2982,3405 ; 2965,3406 2982,3406 ; 2965,3407 2982,3407 ; 2965,3408 2982,3408 ; 2965,3409 2982,3409 ; 2965,3410 2982,3410 ; 2965,3411 2982,3411 ; 2965,3412 2982,3412 ; 2965,3413 2982,3413 ; 2965,3414 2982,3414 ; 2965,3415 2982,3415 ; 2965,3416 2982,3416 ; 2965,3417 2982,3417 ; 2965,3418 2982,3418 ; 2965,3419 2982,3419 ; 2965,3420 2982,3420 ; 2965,3421 2982,3421 ; 2965,3422 2982,3422 ; 2965,3423 2982,3423 ; 2965,3424 2982,3424 ; 2965,3425 2982,3425 ; 2965,3426 2982,3426 ; 2965,3427 2982,3427 ; 2965,3428 2982,3428 ; 2965,3429 2982,3429 ; 2965,3430 2982,3430 ; 2965,3431 2982,3431 ; 2965,3432 2982,3432 ; 2965,3433 2982,3433 ; 2965,3434 2982,3434 ; 2965,3607 3015,3607 ; 2966,3316 2974,3316 ; 2966,3331 2974,3331 ; 2967,3317 2974,3317 ; 2967,3318 2974,3318 ; 2967,3319 2975,3319 ; 2967,3320 2975,3320 ; 2967,3327 2975,3327 ; 2967,3328 2975,3328 ; 2967,3329 2974,3329 ; 2967,3330 2974,3330 ; 2967,3608 3013,3608 ; 2968,3321 2975,3321 ; 2968,3322 2975,3322 ; 2968,3323 2975,3323 ; 2968,3324 2975,3324 ; 2968,3325 2975,3325 ; 2968,3326 2975,3326 ; 2969,3609 3011,3609 ; 2970,3610 3010,3610 ; 2972,3611 3008,3611 ; 2974,3612 3006,3612 ; 2976,3613 3004,3613 ; 2977,3614 3003,3614 ; 2979,3309 2987,3309 ; 2979,3310 2987,3310 ; 2979,3311 2987,3311 ; 2979,3312 2987,3312 ; 2979,3313 2987,3313 ; 2979,3314 2987,3314 ; 2979,3315 2987,3315 ; 2979,3316 2987,3316 ; 2979,3317 2987,3317 ; 2979,3318 2987,3318 ; 2979,3319 2987,3319 ; 2979,3320 2986,3320 ; 2979,3321 2987,3321 ; 2979,3322 3005,3322 ; 2979,3323 3005,3323 ; 2979,3324 3005,3324 ; 2979,3325 3005,3325 ; 2979,3326 3005,3326 ; 2979,3327 3005,3327 ; 2979,3328 2986,3328 ; 2979,3329 2987,3329 ; 2979,3330 2987,3330 ; 2979,3331 2987,3331 ; 2979,3332 2987,3332 ; 2979,3333 2987,3333 ; 2979,3334 2987,3334 ; 2979,3335 2987,3335 ; 2979,3336 2987,3336 ; 2979,3337 2987,3337 ; 2979,3338 2987,3338 ; 2979,3615 3001,3615 ; 2980,3308 2986,3308 ; 2980,3339 2986,3339 ; 2981,3616 2999,3616 ; 2982,3617 2997,3617 ; 2984,3618 2996,3618 ; 2986,3619 2994,3619 ; 2988,3620 2992,3620 ; 2989,3621 2991,3621 ; 2991,3246 3207,3246 ; 2992,3243 3205,3243 ; 2992,3494 3099,3494 ; 2993,3247 3207,3247 ; 2993,3493 3099,3493 ; 2994,3242 3203,3242 ; 2995,3248 3207,3248 ; 2995,3372 3014,3372 ; 2995,3373 3013,3373 ; 2995,3374 3013,3374 ; 2995,3375 3013,3375 ; 2995,3376 3013,3376 ; 2995,3377 3012,3377 ; 2995,3378 3012,3378 ; 2995,3379 3013,3379 ; 2995,3380 3013,3380 ; 2995,3381 3013,3381 ; 2995,3492 3099,3492 ; 2996,3241 3201,3241 ; 2996,3249 3207,3249 ; 2996,3368 3019,3368 ; 2996,3369 3017,3369 ; 2996,3370 3015,3370 ; 2996,3371 3014,3371 ; 2996,3382 3013,3382 ; 2996,3383 3014,3383 ; 2996,3384 3015,3384 ; 2997,3240 3200,3240 ; 2997,3366 3063,3366 ; 2997,3367 3063,3367 ; 2997,3385 3016,3385 ; 2997,3386 3017,3386 ; 2997,3491 3099,3491 ; 2998,3250 3207,3250 ; 2998,3308 3005,3308 ; 2998,3309 3005,3309 ; 2998,3310 3005,3310 ; 2998,3311 3005,3311 ; 2998,3312 3005,3312 ; 2998,3313 3005,3313 ; 2998,3314 3005,3314 ; 2998,3315 3005,3315 ; 2998,3316 3005,3316 ; 2998,3317 3005,3317 ; 2998,3318 3005,3318 ; 2998,3319 3005,3319 ; 2998,3320 3005,3320 ; 2998,3321 3005,3321 ; 2998,3328 3005,3328 ; 2998,3329 3005,3329 ; 2998,3330 3005,3330 ; 2998,3331 3005,3331 ; 2998,3332 3005,3332 ; 2998,3333 3005,3333 ; 2998,3334 3005,3334 ; 2998,3335 3005,3335 ; 2998,3336 3005,3336 ; 2998,3337 3005,3337 ; 2998,3338 3005,3338 ; 2998,3339 3005,3339 ; 2998,3364 3063,3364 ; 2998,3365 3063,3365 ; 2998,3387 3020,3387 ; 2998,3388 3063,3388 ; 2999,3239 3198,3239 ; 2999,3363 3063,3363 ; 2999,3389 3063,3389 ; 2999,3409 3016,3409 ; 2999,3410 3015,3410 ; 2999,3411 3015,3411 ; 2999,3412 3015,3412 ; 2999,3413 3015,3413 ; 2999,3414 3016,3414 ; 2999,3415 3016,3415 ; 2999,3416 3016,3416 ; 2999,3417 3017,3417 ; 2999,3418 3018,3418 ; 2999,3490 3099,3490 ; 3000,3251 3207,3251 ; 3000,3361 3063,3361 ; 3000,3362 3063,3362 ; 3000,3390 3063,3390 ; 3000,3406 3017,3406 ; 3000,3407 3016,3407 ; 3000,3408 3016,3408 ; 3000,3419 3020,3419 ; 3000,3420 3024,3420 ; 3000,3421 3063,3421 ; 3000,3489 3099,3489 ; 3001,3238 3196,3238 ; 3001,3360 3063,3360 ; 3001,3391 3063,3391 ; 3001,3404 3019,3404 ; 3001,3405 3018,3405 ; 3001,3422 3063,3422 ; 3001,3423 3063,3423 ; 3002,3252 3207,3252 ; 3002,3359 3063,3359 ; 3002,3392 3063,3392 ; 3002,3403 3022,3403 ; 3002,3424 3063,3424 ; 3002,3425 3063,3425 ; 3002,3488 3099,3488 ; 3003,3237 3194,3237 ; 3003,3253 3207,3253 ; 3003,3358 3063,3358 ; 3003,3393 3063,3393 ; 3003,3401 3063,3401 ; 3003,3402 3063,3402 ; 3003,3426 3063,3426 ; 3004,3236 3193,3236 ; 3004,3400 3063,3400 ; 3004,3427 3063,3427 ; 3004,3487 3099,3487 ; 3005,3254 3207,3254 ; 3005,3357 3063,3357 ; 3005,3394 3063,3394 ; 3005,3399 3063,3399 ; 3005,3428 3063,3428 ; 3006,3235 3191,3235 ; 3006,3356 3063,3356 ; 3006,3395 3063,3395 ; 3006,3429 3063,3429 ; 3006,3486 3099,3486 ; 3007,3255 3207,3255 ; 3007,3398 3063,3398 ; 3007,3430 3063,3430 ; 3007,3485 3099,3485 ; 3008,3234 3189,3234 ; 3008,3355 3063,3355 ; 3008,3397 3063,3397 ; 3009,3233 3188,3233 ; 3009,3256 3207,3256 ; 3009,3396 3063,3396 ; 3009,3431 3063,3431 ; 3009,3484 3099,3484 ; 3010,3257 3207,3257 ; 3010,3308 3017,3308 ; 3010,3309 3017,3309 ; 3010,3310 3017,3310 ; 3010,3311 3017,3311 ; 3010,3312 3017,3312 ; 3010,3313 3017,3313 ; 3010,3314 3017,3314 ; 3010,3432 3063,3432 ; 3011,3232 3186,3232 ; 3011,3354 3063,3354 ; 3011,3483 3099,3483 ; 3012,3258 3207,3258 ; 3012,3482 3099,3482 ; 3013,3231 3184,3231 ; 3013,3433 3063,3433 ; 3014,3259 3207,3259 ; 3014,3481 3099,3481 ; 3015,3230 3182,3230 ; 3015,3260 3207,3260 ; 3016,3229 3181,3229 ; 3016,3325 3040,3325 ; 3016,3326 3025,3326 ; 3016,3327 3024,3327 ; 3016,3328 3023,3328 ; 3016,3329 3023,3329 ; 3016,3330 3023,3330 ; 3016,3331 3023,3331 ; 3016,3332 3024,3332 ; 3016,3333 3026,3333 ; 3016,3480 3099,3480 ; 3017,3261 3207,3261 ; 3017,3324 3040,3324 ; 3017,3334 3040,3334 ; 3017,3335 3040,3335 ; 3017,3353 3062,3353 ; 3017,3434 3062,3434 ; 3018,3228 3179,3228 ; 3018,3323 3040,3323 ; 3018,3336 3040,3336 ; 3018,3479 3099,3479 ; 3019,3262 3207,3262 ; 3019,3322 3040,3322 ; 3019,3337 3040,3337 ; 3019,3478 3099,3478 ; 3020,3227 3177,3227 ; 3020,3321 3040,3321 ; 3020,3338 3040,3338 ; 3021,3263 3207,3263 ; 3021,3477 3099,3477 ; 3022,3226 3175,3226 ; 3022,3264 3207,3264 ; 3022,3320 3040,3320 ; 3023,3225 3174,3225 ; 3023,3339 3040,3339 ; 3023,3476 3099,3476 ; 3024,3265 3207,3265 ; 3025,3224 3172,3224 ; 3025,3475 3099,3475 ; 3026,3266 3207,3266 ; 3026,3474 3099,3474 ; 3027,3223 3170,3223 ; 3028,3222 3168,3222 ; 3028,3267 3207,3267 ; 3028,3473 3099,3473 ; 3029,3268 3207,3268 ; 3030,3221 3167,3221 ; 3030,3472 3099,3472 ; 3031,3269 3207,3269 ; 3031,3471 3099,3471 ; 3032,3220 3165,3220 ; 3033,3270 3207,3270 ; 3033,3308 3040,3308 ; 3033,3309 3040,3309 ; 3033,3310 3040,3310 ; 3033,3311 3040,3311 ; 3033,3312 3040,3312 ; 3033,3313 3040,3313 ; 3033,3314 3040,3314 ; 3033,3315 3040,3315 ; 3033,3316 3040,3316 ; 3033,3317 3040,3317 ; 3033,3318 3040,3318 ; 3033,3319 3040,3319 ; 3033,3326 3040,3326 ; 3033,3327 3040,3327 ; 3033,3328 3040,3328 ; 3033,3329 3040,3329 ; 3033,3330 3040,3330 ; 3033,3331 3040,3331 ; 3033,3332 3040,3332 ; 3033,3333 3040,3333 ; 3033,3470 3099,3470 ; 3034,3219 3163,3219 ; 3035,3218 3162,3218 ; 3035,3271 3207,3271 ; 3035,3469 3099,3469 ; 3036,3272 3207,3272 ; 3037,3217 3160,3217 ; 3037,3468 3099,3468 ; 3038,3273 3207,3273 ; 3038,3467 3099,3467 ; 3039,3216 3158,3216 ; 3040,3274 3207,3274 ; 3040,3466 3099,3466 ; 3041,3215 3156,3215 ; 3041,3275 3207,3275 ; 3042,3214 3155,3214 ; 3042,3465 3099,3465 ; 3043,3276 3207,3276 ; 3043,3334 3068,3334 ; 3043,3335 3069,3335 ; 3043,3336 3069,3336 ; 3043,3337 3069,3337 ; 3043,3338 3069,3338 ; 3043,3339 3068,3339 ; 3044,3213 3153,3213 ; 3044,3464 3099,3464 ; 3045,3277 3207,3277 ; 3045,3463 3099,3463 ; 3046,3212 3151,3212 ; 3046,3368 3063,3368 ; 3046,3369 3063,3369 ; 3046,3370 3063,3370 ; 3046,3371 3063,3371 ; 3046,3372 3063,3372 ; 3046,3373 3063,3373 ; 3046,3374 3063,3374 ; 3046,3375 3063,3375 ; 3046,3376 3063,3376 ; 3046,3377 3063,3377 ; 3046,3378 3063,3378 ; 3046,3379 3063,3379 ; 3046,3380 3063,3380 ; 3046,3381 3063,3381 ; 3046,3382 3063,3382 ; 3046,3383 3063,3383 ; 3046,3384 3063,3384 ; 3046,3385 3063,3385 ; 3046,3386 3063,3386 ; 3046,3387 3063,3387 ; 3046,3403 3063,3403 ; 3046,3404 3063,3404 ; 3046,3405 3063,3405 ; 3046,3406 3063,3406 ; 3046,3407 3063,3407 ; 3046,3408 3063,3408 ; 3046,3409 3063,3409 ; 3046,3410 3063,3410 ; 3046,3411 3063,3411 ; 3046,3412 3063,3412 ; 3046,3413 3063,3413 ; 3046,3414 3063,3414 ; 3046,3415 3063,3415 ; 3046,3416 3063,3416 ; 3046,3417 3063,3417 ; 3046,3418 3063,3418 ; 3046,3419 3063,3419 ; 3046,3420 3063,3420 ; 3047,3278 3207,3278 ; 3047,3462 3099,3462 ; 3048,3211 3149,3211 ; 3048,3279 3207,3279 ; 3049,3210 3148,3210 ; 3049,3461 3099,3461 ; 3050,3280 3207,3280 ; 3051,3209 3146,3209 ; 3051,3460 3099,3460 ; 3052,3281 3207,3281 ; 3052,3309 3059,3309 ; 3052,3310 3059,3310 ; 3052,3311 3059,3311 ; 3052,3312 3059,3312 ; 3052,3313 3059,3313 ; 3052,3314 3059,3314 ; 3052,3315 3059,3315 ; 3052,3316 3059,3316 ; 3052,3317 3059,3317 ; 3052,3318 3059,3318 ; 3052,3319 3059,3319 ; 3052,3320 3059,3320 ; 3052,3321 3059,3321 ; 3052,3322 3059,3322 ; 3052,3323 3059,3323 ; 3052,3324 3059,3324 ; 3052,3325 3059,3325 ; 3052,3326 3059,3326 ; 3052,3327 3059,3327 ; 3052,3328 3059,3328 ; 3052,3329 3059,3329 ; 3052,3330 3059,3330 ; 3052,3331 3059,3331 ; 3052,3332 3059,3332 ; 3052,3333 3059,3333 ; 3052,3459 3099,3459 ; 3053,3208 3144,3208 ; 3053,3308 3059,3308 ; 3054,3207 3143,3207 ; 3054,3282 3207,3282 ; 3054,3458 3099,3458 ; 3055,3283 3207,3283 ; 3056,3206 3141,3206 ; 3056,3457 3099,3457 ; 3057,3284 3207,3284 ; 3057,3456 3099,3456 ; 3058,3205 3139,3205 ; 3059,3285 3207,3285 ; 3059,3455 3099,3455 ; 3060,3204 3137,3204 ; 3061,3203 3136,3203 ; 3061,3286 3207,3286 ; 3061,3454 3099,3454 ; 3062,3287 3207,3287 ; 3063,3202 3134,3202 ; 3063,3453 3099,3453 ; 3064,3288 3207,3288 ; 3064,3452 3099,3452 ; 3065,3201 3132,3201 ; 3066,3289 3207,3289 ; 3066,3451 3099,3451 ; 3067,3200 3130,3200 ; 3067,3290 3207,3290 ; 3068,3199 3129,3199 ; 3068,3450 3099,3450 ; 3069,3291 3207,3291 ; 3070,3198 3127,3198 ; 3070,3449 3099,3449 ; 3071,3292 3207,3292 ; 3071,3448 3099,3448 ; 3072,3197 3125,3197 ; 3073,3293 3207,3293 ; 3073,3447 3099,3447 ; 3074,3196 3123,3196 ; 3074,3294 3207,3294 ; 3075,3195 3122,3195 ; 3075,3446 3099,3446 ; 3076,3295 3207,3295 ; 3077,3194 3120,3194 ; 3077,3445 3099,3445 ; 3078,3296 3207,3296 ; 3078,3444 3099,3444 ; 3079,3193 3118,3193 ; 3080,3192 3117,3192 ; 3080,3297 3207,3297 ; 3080,3443 3099,3443 ; 3081,3298 3207,3298 ; 3082,3191 3115,3191 ; 3082,3442 3099,3442 ; 3083,3299 3207,3299 ; 3083,3441 3099,3441 ; 3084,3190 3113,3190 ; 3085,3300 3207,3300 ; 3085,3440 3099,3440 ; 3086,3189 3111,3189 ; 3087,3188 3110,3188 ; 3087,3301 3207,3301 ; 3087,3439 3099,3439 ; 3088,3302 3207,3302 ; 3089,3187 3108,3187 ; 3089,3438 3099,3438 ; 3090,3303 3207,3303 ; 3090,3437 3099,3437 ; 3091,3186 3106,3186 ; 3092,3304 3207,3304 ; 3092,3436 3099,3436 ; 3093,3185 3104,3185 ; 3093,3305 3207,3305 ; 3094,3184 3103,3184 ; 3094,3435 3099,3435 ; 3095,3306 3207,3306 ; 3096,3183 3101,3183 ; 3096,3434 3099,3434 ; 3097,3307 3207,3307 ; 3097,3433 3099,3433 ; 3098,3182 3099,3182 ; 3098,3308 3207,3308 ; 3098,3309 3207,3309 ; 3098,3310 3207,3310 ; 3098,3311 3207,3311 ; 3098,3312 3207,3312 ; 3098,3313 3207,3313 ; 3098,3314 3207,3314 ; 3098,3315 3207,3315 ; 3098,3316 3207,3316 ; 3098,3317 3207,3317 ; 3098,3318 3207,3318 ; 3098,3319 3207,3319 ; 3098,3320 3207,3320 ; 3098,3321 3207,3321 ; 3098,3322 3207,3322 ; 3098,3323 3207,3323 ; 3098,3324 3207,3324 ; 3098,3325 3207,3325 ; 3098,3326 3207,3326 ; 3098,3327 3207,3327 ; 3098,3328 3207,3328 ; 3098,3329 3207,3329 ; 3098,3330 3207,3330 ; 3098,3331 3207,3331 ; 3098,3332 3207,3332 ; 3098,3333 3207,3333 ; 3098,3334 3207,3334 ; 3098,3335 3207,3335 ; 3098,3336 3207,3336 ; 3098,3337 3207,3337 ; 3098,3338 3207,3338 ; 3098,3339 3207,3339 ; 3098,3340 3207,3340 ; 3098,3341 3207,3341 ; 3098,3342 3207,3342 ; 3098,3343 3207,3343 ; 3098,3344 3207,3344 ; 3098,3345 3207,3345 ; 3098,3346 3207,3346 ; 3098,3347 3207,3347 ; 3098,3348 3207,3348 ; 3098,3349 3207,3349 ; 3098,3350 3207,3350 ; 3098,3351 3207,3351 ; 3098,3352 3207,3352 ; 3098,3353 3207,3353 ; 3098,3354 3207,3354 ; 3098,3355 3207,3355 ; 3098,3356 3207,3356 ; 3098,3357 3207,3357 ; 3098,3358 3207,3358 ; 3098,3359 3207,3359 ; 3098,3360 3207,3360 ; 3098,3361 3207,3361 ; 3098,3362 3207,3362 ; 3098,3363 3207,3363 ; 3098,3364 3207,3364 ; 3098,3365 3207,3365 ; 3098,3366 3207,3366 ; 3098,3367 3207,3367 ; 3098,3368 3207,3368 ; 3098,3369 3207,3369 ; 3098,3370 3207,3370 ; 3098,3371 3206,3371 ; 3098,3372 3205,3372 ; 3098,3373 3203,3373 ; 3098,3374 3201,3374 ; 3098,3375 3199,3375 ; 3098,3376 3198,3376 ; 3098,3377 3196,3377 ; 3098,3378 3194,3378 ; 3098,3379 3192,3379 ; 3098,3380 3191,3380 ; 3098,3381 3189,3381 ; 3098,3382 3187,3382 ; 3098,3383 3186,3383 ; 3098,3384 3184,3384 ; 3098,3385 3182,3385 ; 3098,3386 3180,3386 ; 3098,3387 3179,3387 ; 3098,3388 3177,3388 ; 3098,3389 3175,3389 ; 3098,3390 3173,3390 ; 3098,3391 3172,3391 ; 3098,3392 3170,3392 ; 3098,3393 3168,3393 ; 3098,3394 3166,3394 ; 3098,3395 3165,3395 ; 3098,3396 3163,3396 ; 3098,3397 3161,3397 ; 3098,3398 3160,3398 ; 3098,3399 3158,3399 ; 3098,3400 3156,3400 ; 3098,3401 3154,3401 ; 3098,3402 3153,3402 ; 3098,3403 3151,3403 ; 3098,3404 3149,3404 ; 3098,3405 3147,3405 ; 3098,3406 3146,3406 ; 3098,3407 3144,3407 ; 3098,3408 3142,3408 ; 3098,3409 3140,3409 ; 3098,3410 3139,3410 ; 3098,3411 3137,3411 ; 3098,3412 3135,3412 ; 3098,3413 3134,3413 ; 3098,3414 3132,3414 ; 3098,3415 3130,3415 ; 3098,3416 3128,3416 ; 3098,3417 3127,3417 ; 3098,3418 3125,3418 ; 3098,3419 3123,3419 ; 3098,3420 3121,3420 ; 3098,3421 3120,3421 ; 3098,3422 3118,3422 ; 3098,3423 3116,3423 ; 3098,3424 3115,3424 ; 3098,3425 3113,3425 ; 3098,3426 3111,3426 ; 3098,3427 3109,3427 ; 3098,3428 3108,3428 ; 3098,3429 3106,3429 ; 3098,3430 3104,3430 ; 3098,3431 3102,3431 ; 3098,3432 3101,3432

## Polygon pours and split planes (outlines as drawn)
no net on Top Overlay "NONET_L-01_P-001" (hatched 45Degree grid 40 track 8): 0,4075
GND on Bottom Layer "GND_L02_P008" (solid, remove dead copper, pour order 8): 0,4075 3970,4075 3970,0 0,0

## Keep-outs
Keep-Out Layer:
  lines w10: 0,0 0,4075 3970,4075 3970,0 0,0 ; 0,0 0,0

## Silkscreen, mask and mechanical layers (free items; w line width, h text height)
Top Overlay:
  text "GND" at 3760,1525 h50
  text "GND" at 3760,1415 h50
  text "GND" at 3760,1315 h50
  text "ROUT" at 3760,1220 h50
  text "TIN" at 3765,1115 h50
  text "RIN" at 3245,945 h50 r90
  text "GND" at 3345,940 h50 r90
  text "GND" at 3445,940 h50 r90
  text "GND" at 3540,940 h50 r90
  text "TOUT" at 3145,890 h50 r90

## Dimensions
3615,800 to 3730,-380 on Top Overlay
3055,745 to 3730,-535 on Top Overlay
3730,945 to 3845,770 on Top Overlay
4275,1605 to 5015,1095 on Top Overlay
4735,125 to 4025,1095 on Top Overlay
3845,3955 to 3845,125 on Top Overlay
125,125 to 3845,125 on Top Overlay
-120,0 to -165,4075 on Top Overlay
0,-95 to 3970,-40 on Top Overlay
